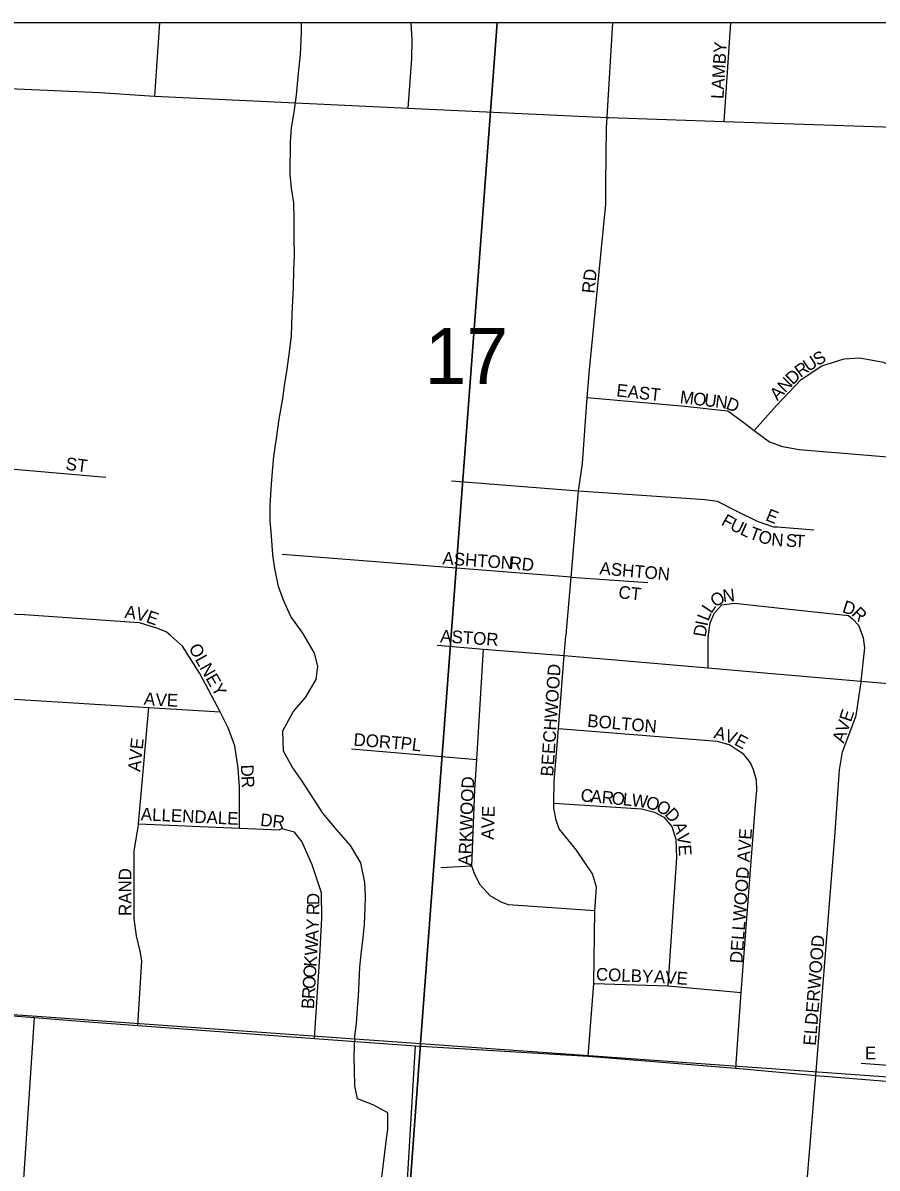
# Model space of a CAD drawing. Extents: x 0 to 34, y 0 to 22.
# Drawn here: x 5.595 to 6.235, y 20.042 to 20.9 of the extents above; entities that cross this region are included whole.
import ezdxf

# ---------------------------------------------------------------- set-up
doc = ezdxf.new("R2010")
doc.units = 0
for name, color, linetype in [('GM_X_City_Street', 7, 'Continuous'), ('GM_X_City_Street_Text', 7, 'Continuous'), ('GM_X_Minor_River', 7, 'Continuous'), ('GM_X_Section', 7, 'Continuous'), ('GM_X_Section_Text', 7, 'Continuous'), ('GM_X_Township', 7, 'Continuous'), ('GM_X_US_Route', 7, 'Continuous')]:
    doc.layers.add(name, color=color, linetype=linetype)

msp = doc.modelspace()

# ---------------------------------------------------------------- linework, layer by layer
at = {"layer": 'GM_X_City_Street'}
for points in [[(5.69384, 20.84521), (5.69741, 20.9)], [(5.88349, 20.83613), (5.88613, 20.87314), (5.88639, 20.88744), (5.88559, 20.9)], [(6.03245, 20.82974), (6.03676, 20.9)], [(6.12003, 20.82625), (6.12503, 20.9)], [(6.03157, 20.77966), (6.03195, 20.82166), (6.03241, 20.82919), (6.03245, 20.82965), (6.03245, 20.82974)], [(6.01405, 20.57006), (6.01761, 20.61934), (6.01911, 20.64016), (6.03143, 20.76434), (6.03157, 20.77942), (6.03157, 20.77966)], [(6.14243, 20.59481), (6.15933, 20.61333), (6.17772, 20.63292), (6.19317, 20.64311), (6.21, 20.64832), (6.22177, 20.64911), (6.23949, 20.64595), (6.25442, 20.63792), (6.27011, 20.63026), (6.28103, 20.62766), (6.31132, 20.6251), (6.3729, 20.6199), (6.43442, 20.61862)], [(6.01761, 20.61934), (6.09072, 20.61303), (6.10669, 20.61124)], [(6.10669, 20.61124), (6.10823, 20.61106), (6.11339, 20.61048), (6.12283, 20.60945), (6.13396, 20.60116), (6.14243, 20.59481), (6.154, 20.58615), (6.16375, 20.58283), (6.17619, 20.58057), (6.27866, 20.57192)], [(5.42222, 20.58122), (5.52552, 20.57126), (5.65709, 20.55987)], [(6.0017, 20.44158), (6.00543, 20.48487), (6.011, 20.54964), (6.01405, 20.57006)], [(5.91588, 20.55696), (6.011, 20.54964), (6.10575, 20.54312), (6.1148, 20.54172), (6.12899, 20.53447), (6.1447, 20.5268), (6.15708, 20.52265), (6.16011, 20.52257), (6.18733, 20.52026)], [(6.00543, 20.48487), (5.7892, 20.50176)], [(6.00543, 20.48487), (6.06301, 20.48094)], [(5.41035, 20.44655), (5.50846, 20.44038), (5.51603, 20.44017), (5.52331, 20.44261), (5.54943, 20.45477), (5.56317, 20.45817), (5.59611, 20.45684), (5.68197, 20.45094), (5.694, 20.44718)], [(6.10822, 20.41695), (6.10805, 20.43977), (6.10951, 20.45074), (6.11276, 20.45824), (6.11824, 20.46416), (6.12775, 20.46541), (6.15986, 20.46182), (6.21314, 20.4561), (6.2161, 20.45374), (6.22088, 20.44867)], [(5.75709, 20.29694), (5.75724, 20.32764), (5.75613, 20.34172), (5.75359, 20.3585), (5.74867, 20.37193), (5.74257, 20.38388), (5.72749, 20.41279), (5.71444, 20.43329), (5.70557, 20.44115), (5.70224, 20.4439), (5.694, 20.44718)], [(6.0182, 20.12601), (6.02237, 20.18053), (6.02335, 20.23487), (6.02455, 20.25271), (6.02143, 20.26267), (6.00944, 20.28049), (5.99664, 20.29642), (5.99417, 20.30295), (5.99253, 20.31173), (5.99257, 20.31553), (5.99273, 20.33185), (5.99596, 20.37162), (6.00038, 20.42612), (6.00161, 20.44054), (6.0017, 20.44158)], [(6.18862, 20.1117), (6.20303, 20.29047), (6.20638, 20.34049), (6.20867, 20.35409), (6.21276, 20.36461), (6.21892, 20.38114), (6.22268, 20.40609), (6.22278, 20.40705), (6.22532, 20.43183), (6.22441, 20.43945), (6.22088, 20.44867)], [(5.90511, 20.43387), (5.93992, 20.43104), (6.00038, 20.42612), (6.03556, 20.42327), (6.10822, 20.41695), (6.15314, 20.41304), (6.22278, 20.40705), (6.24925, 20.40479), (6.25236, 20.40452)], [(6.02335, 20.23487), (5.9586, 20.23943), (5.95297, 20.24148), (5.94477, 20.24628), (5.93743, 20.25446), (5.93348, 20.26217), (5.93101, 20.26832), (5.93342, 20.32559), (5.93483, 20.34833), (5.93992, 20.43104)], [(5.40749, 20.40121), (5.4814, 20.39598), (5.52037, 20.39372), (5.52873, 20.39423), (5.54621, 20.39601), (5.55983, 20.39524), (5.68921, 20.38719), (5.74257, 20.38388)], [(5.68136, 20.29772), (5.68157, 20.30022), (5.68419, 20.33089), (5.68921, 20.38719)], [(5.99596, 20.37162), (6.1149, 20.36212), (6.12429, 20.35919), (6.13024, 20.35522), (6.13434, 20.35282)], [(5.84108, 20.35636), (5.93483, 20.34833)], [(6.12873, 20.11707), (6.13272, 20.17371), (6.14345, 20.31421), (6.14453, 20.32519), (6.14437, 20.33279), (6.14194, 20.34045), (6.13982, 20.34583), (6.13434, 20.35282)], [(5.99257, 20.31553), (6.05809, 20.31136), (6.06787, 20.3088), (6.07497, 20.30517), (6.08083, 20.29817), (6.08396, 20.28859), (6.08432, 20.27491), (6.07779, 20.17874)], [(5.68104, 20.14893), (5.68393, 20.19751), (5.68273, 20.20466), (5.68005, 20.21628), (5.67826, 20.22909), (5.67815, 20.2798), (5.68112, 20.29616), (5.68131, 20.29718), (5.68136, 20.29772)], [(5.68157, 20.30022), (5.75709, 20.29694), (5.78701, 20.29564)], [(5.81336, 20.13935), (5.81724, 20.20098), (5.81882, 20.22941), (5.81862, 20.24841), (5.81165, 20.26949), (5.80381, 20.28681), (5.79833, 20.2938), (5.78855, 20.29636), (5.78701, 20.29564)], [(5.93101, 20.26832), (5.90785, 20.2671)], [(4.84273, 20.21193), (4.89767, 20.20741), (5.04406, 20.19597), (5.07836, 20.1943), (5.14221, 20.19039), (5.16772, 20.18803), (5.20299, 20.18608), (5.26506, 20.18174), (5.39048, 20.17298), (5.49413, 20.16358), (5.60374, 20.15512), (5.63143, 20.1529)], [(6.02237, 20.18053), (6.07779, 20.17874), (6.13272, 20.17371)], [(5.80359, 19.65605), (5.80446, 19.66792), (5.8027, 19.67972), (5.79788, 19.69042), (5.79435, 19.69562), (5.79191, 19.69923), (5.7787, 19.7066), (5.73528, 19.72646), (5.72018, 19.73461), (5.69771, 19.74367), (5.68288, 19.75935), (5.63982, 19.81266), (5.60953, 19.85328), (5.58912, 19.89456), (5.58629, 19.91283), (5.58725, 19.92508), (5.58984, 19.9584), (5.59103, 19.97359), (5.59499, 20.02446), (5.59517, 20.02675), (5.60374, 20.15512)], [(5.63143, 20.1529), (5.68104, 20.14893), (5.81336, 20.13935), (5.88898, 20.13374)], [(5.88125, 20.00389), (5.88898, 20.13374)], [(5.88898, 20.13374), (6.0182, 20.12601), (6.12873, 20.11707), (6.18862, 20.1117), (6.3069, 20.10217), (6.39285, 20.09457), (6.47955, 20.0881), (6.49452, 20.08705), (6.61958, 20.07678), (6.81532, 20.06158), (6.83409, 20.06038), (6.90291, 20.05472)], [(6.22275, 20.12091), (6.39407, 20.10799), (6.62166, 20.09018), (6.83524, 20.07281), (6.86941, 20.07033)], [(6.22293, 19.803), (6.22096, 19.80608), (6.21649, 19.81309), (6.21059, 19.82874), (6.20855, 19.85005), (6.20715, 19.85237), (6.20185, 19.86114), (6.18612, 19.87994), (6.17681, 19.89601), (6.17391, 19.90783), (6.17378, 19.92987), (6.18862, 20.1117)]]:
    msp.add_lwpolyline(points, dxfattribs=at)
at = {"layer": 'GM_X_Minor_River'}
msp.add_lwpolyline([(5.86361, 20.0355), (5.86689, 20.06204), (5.86811, 20.07152), (5.86823, 20.08367), (5.85768, 20.08944), (5.84561, 20.0941), (5.84343, 20.10398), (5.84316, 20.11575), (5.84288, 20.12562), (5.84341, 20.14118), (5.84463, 20.15066), (5.84549, 20.16166), (5.84634, 20.17114), (5.84682, 20.18139), (5.8473, 20.19277), (5.84816, 20.20263), (5.84938, 20.21249), (5.85064, 20.22501), (5.85113, 20.23639), (5.8516, 20.24587), (5.85094, 20.25613), (5.84805, 20.27095), (5.84022, 20.28392), (5.82973, 20.29577), (5.81963, 20.308), (5.81067, 20.32212), (5.80358, 20.3328), (5.79648, 20.34273), (5.79016, 20.35454), (5.78954, 20.36973), (5.79725, 20.38409), (5.80644, 20.39464), (5.81452, 20.40824), (5.81575, 20.4181), (5.81319, 20.42799), (5.80463, 20.44286), (5.79566, 20.45545), (5.79009, 20.46765), (5.78641, 20.47792), (5.7835, 20.49123), (5.78209, 20.50149), (5.78109, 20.51592), (5.78006, 20.52731), (5.78017, 20.5387), (5.78108, 20.55463), (5.78193, 20.56411), (5.78279, 20.57511), (5.78481, 20.58876), (5.78684, 20.60316), (5.78964, 20.6187), (5.79086, 20.62818), (5.79288, 20.64068), (5.79491, 20.65547), (5.79614, 20.6657), (5.79668, 20.68202), (5.79762, 20.70174), (5.79774, 20.71465), (5.79823, 20.72603), (5.79797, 20.73893), (5.79811, 20.75297), (5.79784, 20.76512), (5.79606, 20.77614), (5.79502, 20.7864), (5.79525, 20.81068), (5.79611, 20.8213), (5.79811, 20.83305), (5.79975, 20.84594), (5.80142, 20.86224), (5.80269, 20.87627), (5.8036, 20.89258), (5.80367, 20.9)], dxfattribs=at)
at = {"layer": 'GM_X_Section'}
for p, q in [((5.95003, 20.9), (5.44435, 20.9)), ((6.4544, 20.9), (5.95003, 20.9))]:
    msp.add_line(p, q, dxfattribs=at)
for points in [[(5.44435, 20.9), (5.39107, 20.17129), (5.8928, 20.13549), (5.95003, 20.9)], [(5.95003, 20.9), (5.8928, 20.13549), (6.39308, 20.09979), (6.4544, 20.9)]]:
    msp.add_lwpolyline(points, dxfattribs=at)
for points in [[(5.39107, 20.17129), (5.8928, 20.13549), (5.81902, 19.1295), (5.31842, 19.16738)], [(5.8928, 20.13549), (6.39308, 20.09979), (6.31814, 19.09172), (5.81902, 19.1295)]]:
    msp.add_lwpolyline(points, close=True, dxfattribs=at)
at = {"layer": 'GM_X_Township'}
msp.add_lwpolyline([(9.4, 17.82945), (9.4, 20.9), (4.42993, 20.9)], dxfattribs=at)
at = {"layer": 'GM_X_US_Route'}
msp.add_lwpolyline([(5.49118, 20.85512), (5.52807, 20.85345), (5.65258, 20.84779), (5.68974, 20.8454), (5.69384, 20.84521), (5.88349, 20.83613), (6.03241, 20.82919), (6.03369, 20.82914), (6.12003, 20.82625), (6.32153, 20.81951), (6.32492, 20.81934), (6.44983, 20.81341), (6.50608, 20.81127), (6.55995, 20.8089), (6.61605, 20.80495), (6.66585, 20.80248), (6.66772, 20.80239), (6.731, 20.7995), (6.75673, 20.79832), (6.8528, 20.79392), (6.85574, 20.7938), (6.95519, 20.7898)], dxfattribs=at)

# ---------------------------------------------------------------- texts
at = {"layer": 'GM_X_City_Street_Text'}
for s, height, rotation, p in [('LAMBY', 0.00947, 86.56383, (6.11957, 20.84283)), ('RD', 0.00947, 83.99338, (6.02288, 20.69708)), ('U', 0.00947, 33.07791, (6.18316, 20.63832)), ('S', 0.00947, 29.67032, (6.19002, 20.64279)), ('D', 0.00947, 44.14997, (6.17147, 20.62843)), ('R', 0.00947, 35.79172, (6.17717, 20.634)), ('EAST', 0.00947, 353.47756, (6.03902, 20.62034)), ('N', 0.00947, 46.26753, (6.16578, 20.62247)), ('M', 0.00947, 352.9518, (6.08654, 20.61533)), ('O', 0.00947, 352.97163, (6.09647, 20.61411)), ('U', 0.00947, 353.05113, (6.10476, 20.61308)), ('N', 0.00947, 353.05392, (6.11303, 20.61207)), ('A', 0.00947, 46.26753, (6.16002, 20.61645)), ('D', 0.00947, 339.05508, (6.12071, 20.61121)), ('ST', 0.00947, 352.8649, (5.62654, 20.56534)), ('E', 0.00947, 337.93484, (6.15045, 20.52766)), ('F', 0.00947, 330.73305, (6.11725, 20.52442)), ('U', 0.00947, 334.28626, (6.12363, 20.52086)), ('L', 0.00947, 335.39415, (6.13132, 20.51716)), ('T', 0.00947, 339.57635, (6.13809, 20.5141)), ('O', 0.00947, 341.94192, (6.14473, 20.51163)), ('N', 0.00947, 355.91649, (6.15512, 20.50856)), ('S', 0.00947, 356.44582, (6.16603, 20.50781)), ('T', 0.00947, 356.33676, (6.17268, 20.5074)), ('ASHTON', 0.00947, 355.9166, (5.90895, 20.49451)), ('RD', 0.00947, 353.98321, (5.959, 20.49117)), ('ASHTON', 0.00947, 354.89673, (6.02648, 20.487)), ('CT', 0.00947, 353.65048, (6.04055, 20.46914)), ('N', 0.00947, 6.13258, (6.1194, 20.46601)), ('O', 0.00947, 32.33205, (6.11343, 20.46193)), ('D', 0.00947, 342.43604, (6.20793, 20.45873)), ('A', 0.00947, 351.57623, (5.67072, 20.45449)), ('V', 0.00947, 345.70928, (5.67872, 20.45332)), ('E', 0.00947, 340.64937, (5.68658, 20.45133)), ('L', 0.00947, 67.93483, (6.1082, 20.45138)), ('L', 0.00947, 56.25689, (6.11047, 20.45711)), ('R', 0.00947, 315.65263, (6.21488, 20.45682)), ('D', 0.00947, 80.82512, (6.10621, 20.4396)), ('I', 0.00947, 78.78434, (6.10752, 20.44774)), ('ASTOR', 0.00947, 356.27076, (5.90727, 20.43617)), ('OLNEY', 0.00947, 299.2996, (5.71873, 20.43189)), ('BEECHWOOD', 0.00947, 86.14289, (5.99204, 20.33535)), ('A', 0.00947, 353.86742, (5.68522, 20.38944)), ('V', 0.00947, 357.44828, (5.69415, 20.3885)), ('E', 0.00947, 357.71751, (5.70253, 20.38813)), ('BOLTON', 0.00947, 354.9006, (6.01731, 20.37284)), ('E', 0.00947, 71.72276, (6.21505, 20.37586)), ('A', 0.00947, 345.00945, (6.11171, 20.36447)), ('V', 0.00947, 71.15037, (6.21233, 20.36787)), ('AVE', 0.00947, 84.09694, (5.68288, 20.33875)), ('DORT', 0.00947, 355.48255, (5.84229, 20.35867)), ('PL', 0.00947, 352.87835, (5.87737, 20.35616)), ('V', 0.00947, 340.05798, (6.11955, 20.36238)), ('E', 0.00947, 331.45496, (6.12704, 20.35969)), ('A', 0.00947, 71.17105, (6.20964, 20.35999)), ('D', 0.00947, 272.47057, (5.7581, 20.34429)), ('R', 0.00947, 273.32073, (5.75846, 20.33581)), ('ARKWOOD', 0.00947, 87.67966, (5.93037, 20.26864)), ('C', 0.00947, 354.62529, (6.0123, 20.31701)), ('A', 0.00947, 354.63124, (6.01977, 20.3163)), ('R', 0.00947, 354.62529, (6.02807, 20.31553)), ('O', 0.00947, 354.61561, (6.03553, 20.31482)), ('L', 0.00947, 354.62982, (6.04383, 20.31404)), ('W', 0.00947, 352.59759, (6.05038, 20.31343)), ('O', 0.00947, 345.2164, (6.06081, 20.31209)), ('ALLENDALE', 0.00947, 357.24229, (5.68307, 20.30281)), ('AVE', 0.00947, 88.02609, (5.94748, 20.28806)), ('O', 0.00947, 332.61398, (6.06835, 20.31017)), ('D', 0.00947, 312.49569, (6.07506, 20.30686)), ('DR', 0.00947, 353.66381, (5.77235, 20.29863)), ('A', 0.00947, 289.87292, (6.08168, 20.29956)), ('DELLWOOD AVE', 0.0094697, 85.87799, (6.13371, 20.19536)), ('V', 0.00947, 279.90795, (6.0844, 20.29214)), ('E', 0.00947, 273.74503, (6.0858, 20.2842)), ('RAND', 0.00947, 90, (5.6762, 20.23106)), ('D', 0.00947, 89.99284, (5.81704, 20.23919)), ('R', 0.00947, 89.6733, (5.81699, 20.23163)), ('Y', 0.00947, 86.89652, (5.81646, 20.22032)), ('A', 0.00947, 86.52317, (5.81595, 20.21193)), ('W', 0.00947, 86.54105, (5.8153, 20.20111)), ('ELDERWOOD', 0.00947, 85.45203, (6.18871, 20.1337)), ('K', 0.00947, 86.52317, (5.81479, 20.19279)), ('O', 0.00947, 86.52317, (5.81429, 20.18447)), ('COLBY', 0.00947, 357.56473, (6.02389, 20.18284)), ('O', 0.00947, 86.53643, (5.81378, 20.17615)), ('AVE', 0.00947, 356.05455, (6.06731, 20.18117)), ('R', 0.00947, 86.53432, (5.81333, 20.16866)), ('B', 0.00947, 86.52515, (5.81287, 20.16118)), ('E', 0.00947, 0.00001, (6.22548, 20.12367))]:
    msp.add_text(s, height=height, rotation=rotation, dxfattribs=at).set_placement(p)
at = {"layer": 'GM_X_Section_Text'}
msp.add_text('17', height=0.041856, rotation=0.00001, dxfattribs=at).set_placement((5.8959, 20.62956))

doc.saveas('drawing.dxf')
